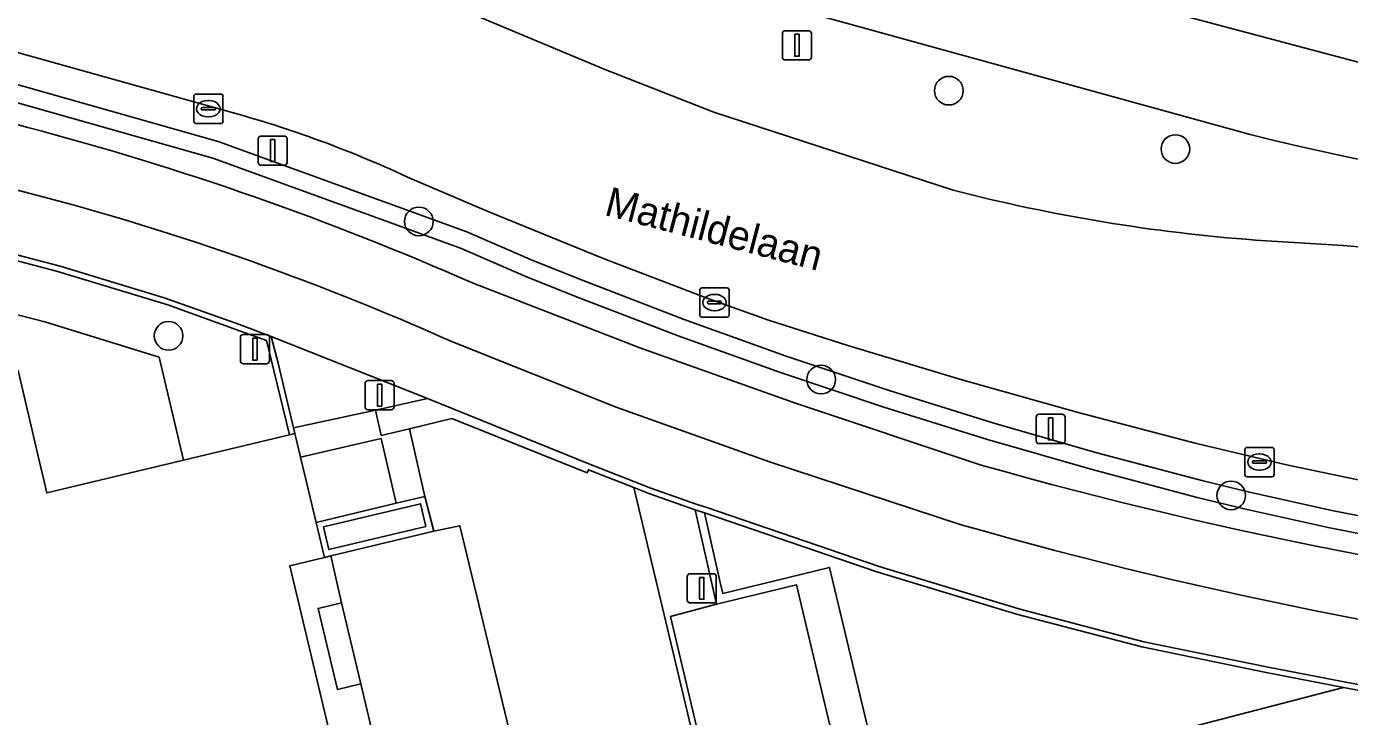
# Model space of a CAD drawing. Extents: x 160675 to 161153, y 383241 to 383714.
# Drawn here: x 160904.77 to 160949.96, y 383538.04 to 383561.62 of the extents above; entities that cross this region are included whole.
import ezdxf

# ---------------------------------------------------------------- set-up
doc = ezdxf.new("R2010")
doc.units = 0
for name, color, linetype in [('IMGEO_Berm_groen', 7, 'Continuous'), ('IMGEO_Boom', 7, 'Continuous'), ('IMGEO_Fietspad_gesloten', 7, 'Continuous'), ('IMGEO_Groenvoorziening', 7, 'Continuous'), ('IMGEO_Haag', 7, 'Continuous'), ('IMGEO_Kolk', 7, 'Continuous'), ('IMGEO_Lichtmast', 7, 'Continuous'), ('IMGEO_Muur', 7, 'Continuous'), ('IMGEO_Openbare_ruimte_label', 7, 'Continuous'), ('IMGEO_OVBaan_gesloten', 7, 'Continuous'), ('IMGEO_Pand', 7, 'Continuous'), ('IMGEO_Parkeervlak_open', 7, 'Continuous'), ('IMGEO_Rijbaan_lokaal_gesloten', 7, 'Continuous'), ('IMGEO_Rijbaan_lokaal_open', 7, 'Continuous'), ('IMGEO_Voetpad_op_trap', 7, 'Continuous'), ('IMGEO_Voetpad_open', 7, 'Continuous')]:
    doc.layers.add(name, color=color, linetype=linetype)

msp = doc.modelspace()

# ---------------------------------------------------------------- linework, layer by layer
at = {"layer": 'IMGEO_Berm_groen'}
for points in [[(160946.568, 383557.927), (160870.684, 383578.867)], [(160877.407, 383567.315), (160911.318, 383557.69), (160919.816, 383554.602), (160922.07, 383553.628), (160923.782, 383552.939), (160927.24, 383551.612), (160930.725, 383550.359), (160934.237, 383549.182), (160937.774, 383548.081), (160941.333, 383547.057), (160944.917, 383546.109), (160946.496, 383545.722), (160949.354, 383545.086), (160952.227, 383544.527)], [(160952.121, 383543.937), (160949.232, 383544.498), (160946.36, 383545.138), (160944.763, 383545.529), (160941.173, 383546.479), (160937.602, 383547.507), (160934.053, 383548.612), (160930.529, 383549.793), (160927.032, 383551.05), (160923.562, 383552.381), (160921.832, 383553.078), (160919.594, 383554.044), (160911.134, 383557.118), (160877.247, 383566.736)], [(160877.012, 383565.887), (160904.814, 383558.169)], [(160918.949, 383562.487), (160924.508, 383560.159), (160928.246, 383558.692), (160936.421, 383556.028)], [(160911.387, 383558.791), (160899.725, 383562.047)], [(160924.508, 383553.676), (160920.566, 383555.292), (160917.783, 383556.475)], [(160946.753, 383554.323), (160949.749, 383554.139), (160953.703, 383553.792), (160955.745, 383553.521)], [(160963.712, 383543.929), (160962.174, 383544.134), (160958.901, 383544.607), (160954.757, 383545.293), (160950.907, 383545.998), (160947.811, 383546.648), (160944.738, 383547.376), (160940.695, 383548.433), (160936.687, 383549.561), (160932.828, 383550.717), (160930.113, 383551.585), (160927.984, 383552.348), (160924.508, 383553.676)], [(160920.031, 383552.846), (160925.725, 383550.641), (160931.005, 383548.758), (160937.384, 383546.634)]]:
    msp.add_lwpolyline(points, dxfattribs=at)
for centre, radius, start, end in [((160901.669, 383521.963), 38.088, 64.9714, 75.2178), ((160878.698, 383459.098), 102.456, 66.20752, 75.23218), ((160969.146, 383648.782), 93.619, 256.04461, 272.62543), ((160951.121, 383612.952), 58.792, 255.52003, 265.73883), ((160978.636, 383692.084), 151.187, 254.16588, 264.20861)]:
    msp.add_arc(centre, radius, start, end, dxfattribs=at)
at = {"layer": 'IMGEO_Boom'}
for centre in [(160936.275, 383559.427), (160944.015, 383557.431), (160918.172, 383554.958), (160909.623, 383551.05), (160931.915, 383549.555), (160945.921, 383545.599)]:
    msp.add_circle(centre, 0.489, dxfattribs=at)
at = {"layer": 'IMGEO_Fietspad_gesloten'}
for points in [[(160904.814, 383558.169), (160877.012, 383565.887), (160875.567, 383566.288), (160873.601, 383566.834), (160872.54, 383567.128), (160754.374, 383598.874)], [(160937.384, 383546.634), (160931.005, 383548.758), (160925.725, 383550.641), (160920.031, 383552.846)], [(160919.266, 383550.863), (160924.913, 383548.61), (160930.147, 383546.745), (160936.693, 383544.597)]]:
    msp.add_lwpolyline(points, dxfattribs=at)
for centre, radius, start, end in [((160878.698, 383459.098), 102.456, 66.20752, 75.23218), ((160881.804, 383467.296), 91.58, 65.85393, 75.70457), ((160978.636, 383692.084), 151.187, 254.16588, 264.20861), ((160979.162, 383693.061), 154.418, 254.03661, 263.90206)]:
    msp.add_arc(centre, radius, start, end, dxfattribs=at)
at = {"layer": 'IMGEO_Groenvoorziening'}
for points in [[(160952.227, 383544.527), (160949.354, 383545.086), (160946.496, 383545.722), (160944.917, 383546.109), (160941.333, 383547.057), (160937.774, 383548.081), (160934.237, 383549.182), (160930.725, 383550.359), (160927.24, 383551.612), (160923.782, 383552.939), (160922.07, 383553.628), (160919.816, 383554.602), (160911.318, 383557.69), (160877.407, 383567.315)], [(160877.247, 383566.736), (160911.134, 383557.118), (160919.594, 383554.044), (160921.832, 383553.078), (160923.562, 383552.381), (160927.032, 383551.05), (160930.529, 383549.793), (160934.053, 383548.612), (160937.602, 383547.507), (160941.173, 383546.479), (160944.763, 383545.529), (160946.36, 383545.138), (160949.232, 383544.498), (160952.121, 383543.937)]]:
    msp.add_lwpolyline(points, dxfattribs=at)
for points in [[(160898.183, 383555.263), (160897.705, 383553.477), (160898.647, 383553.196), (160898.676, 383553.288), (160904.25, 383551.83), (160905.399, 383551.525), (160909.301, 383550.316), (160910.13, 383546.802), (160913.753, 383547.673), (160913.116, 383550.287), (160912.969, 383550.889), (160912.211, 383551.165), (160909.597, 383552.11), (160905.791, 383553.265)], [(160914.917, 383544.524), (160915.101, 383543.748), (160918.409, 383544.536), (160918.225, 383545.312)], [(160927.934, 383545.001), (160928.47, 383542.621), (160928.556, 383542.241), (160932.199, 383543.135), (160934.144, 383534.982), (160949.761, 383539.035), (160947.11, 383539.546), (160942.863, 383540.421), (160938.591, 383541.539), (160933.821, 383542.992)], [(160915.531, 383541.927), (160914.733, 383541.738), (160915.39, 383538.969), (160916.187, 383539.158)]]:
    msp.add_lwpolyline(points, close=True, dxfattribs=at)
at = {"layer": 'IMGEO_Haag'}
for points in [[(160952.227, 383544.527), (160949.354, 383545.086), (160946.496, 383545.722), (160944.917, 383546.109), (160941.333, 383547.057), (160937.774, 383548.081), (160934.237, 383549.182), (160930.725, 383550.359), (160927.24, 383551.612), (160923.782, 383552.939), (160922.07, 383553.628), (160919.816, 383554.602), (160911.318, 383557.69), (160877.407, 383567.315)], [(160877.247, 383566.736), (160911.134, 383557.118), (160919.594, 383554.044), (160921.832, 383553.078), (160923.562, 383552.381), (160927.032, 383551.05), (160930.529, 383549.793), (160934.053, 383548.612), (160937.602, 383547.507), (160941.173, 383546.479), (160944.763, 383545.529), (160946.36, 383545.138), (160949.232, 383544.498), (160952.121, 383543.937)]]:
    msp.add_lwpolyline(points, dxfattribs=at)
at = {"layer": 'IMGEO_Kolk'}
for p, q in [((160910.482, 383558.384), (160910.482, 383559.236)), ((160910.557, 383559.31), (160911.409, 383559.31)), ((160910.97, 383559.09), (160910.995, 383559.09)), ((160911.483, 383559.236), (160911.483, 383558.384)), ((160910.741, 383558.804), (160910.741, 383558.816)), ((160911.179, 383558.767), (160910.781, 383558.767)), ((160910.784, 383558.853), (160911.182, 383558.853)), ((160910.993, 383558.53), (160910.968, 383558.53)), ((160911.225, 383558.816), (160911.225, 383558.804)), ((160911.409, 383558.31), (160910.557, 383558.31)), ((160927.844, 383552.688), (160928.696, 383552.688)), ((160927.769, 383551.762), (160927.769, 383552.614)), ((160928.028, 383552.182), (160928.028, 383552.194)), ((160928.071, 383552.231), (160928.469, 383552.231)), ((160928.257, 383552.468), (160928.282, 383552.468)), ((160928.512, 383552.194), (160928.512, 383552.182)), ((160928.77, 383552.614), (160928.77, 383551.762)), ((160928.466, 383552.145), (160928.068, 383552.145)), ((160928.28, 383551.908), (160928.255, 383551.908)), ((160928.696, 383551.688), (160927.844, 383551.688)), ((160946.461, 383547.237), (160947.313, 383547.237)), ((160946.386, 383546.311), (160946.386, 383547.163)), ((160946.645, 383546.731), (160946.645, 383546.743)), ((160946.688, 383546.78), (160947.086, 383546.78)), ((160946.874, 383547.017), (160946.899, 383547.017)), ((160947.129, 383546.743), (160947.129, 383546.731)), ((160947.387, 383547.163), (160947.387, 383546.311)), ((160947.083, 383546.694), (160946.685, 383546.694)), ((160946.897, 383546.457), (160946.872, 383546.457)), ((160947.313, 383546.237), (160946.461, 383546.237))]:
    msp.add_line(p, q, dxfattribs=at)
for points in [[(160910.482, 383558.384), (160910.482, 383559.236)], [(160910.557, 383559.31), (160911.409, 383559.31)], [(160911.483, 383559.236), (160911.483, 383558.384)], [(160911.409, 383558.31), (160910.557, 383558.31)], [(160927.844, 383552.688), (160928.696, 383552.688)], [(160927.769, 383551.762), (160927.769, 383552.614)], [(160928.77, 383552.614), (160928.77, 383551.762)], [(160928.696, 383551.688), (160927.844, 383551.688)], [(160946.461, 383547.237), (160947.313, 383547.237)], [(160946.386, 383546.311), (160946.386, 383547.163)], [(160947.387, 383547.163), (160947.387, 383546.311)], [(160947.313, 383546.237), (160946.461, 383546.237)]]:
    msp.add_lwpolyline(points, dxfattribs=at)
for centre, radius, start, end in [((160910.559, 383559.234), 0.0765, 91.552, 178.448), ((160910.559, 383559.234), 0.0765, 91.552, 178.448), ((160911.407, 383559.234), 0.0765, 1.552, 88.448), ((160911.407, 383559.234), 0.0765, 1.552, 88.448), ((160910.781, 383558.813), 0.0403, 85.8775, 175.7526), ((160910.778, 383558.803), 0.0366, 178.938, 274.7102), ((160911.182, 383558.81), 0.043, 264.8664, 352.4533), ((160911.186, 383558.815), 0.0386, 1.7309, 96.639), ((160910.559, 383558.386), 0.0765, 181.552, 268.448), ((160910.559, 383558.386), 0.0765, 181.552, 268.448), ((160911.407, 383558.386), 0.0765, 271.552, 358.448), ((160911.407, 383558.386), 0.0765, 271.552, 358.448), ((160927.846, 383552.612), 0.0765, 91.552, 178.448), ((160927.846, 383552.612), 0.0765, 91.552, 178.448), ((160928.694, 383552.612), 0.0765, 1.552, 88.448), ((160928.694, 383552.612), 0.0765, 1.552, 88.448), ((160928.068, 383552.191), 0.0403, 85.8775, 175.7526), ((160928.065, 383552.181), 0.0366, 178.938, 274.7102), ((160928.469, 383552.188), 0.043, 264.8664, 352.4533), ((160928.473, 383552.193), 0.0386, 1.7309, 96.639), ((160927.846, 383551.764), 0.0765, 181.552, 268.448), ((160927.846, 383551.764), 0.0765, 181.552, 268.448), ((160928.694, 383551.764), 0.0765, 271.552, 358.448), ((160928.694, 383551.764), 0.0765, 271.552, 358.448), ((160946.463, 383547.161), 0.0765, 91.552, 178.448), ((160946.463, 383547.161), 0.0765, 91.552, 178.448), ((160947.311, 383547.161), 0.0765, 1.552, 88.448), ((160947.311, 383547.161), 0.0765, 1.552, 88.448), ((160946.685, 383546.74), 0.0403, 85.8775, 175.7526), ((160947.09, 383546.742), 0.0386, 1.7309, 96.639), ((160946.463, 383546.313), 0.0765, 181.552, 268.448), ((160946.463, 383546.313), 0.0765, 181.552, 268.448), ((160946.682, 383546.73), 0.0366, 178.938, 274.7102), ((160947.086, 383546.737), 0.043, 264.8664, 352.4533), ((160947.311, 383546.313), 0.0765, 271.552, 358.448), ((160947.311, 383546.313), 0.0765, 271.552, 358.448)]:
    msp.add_arc(centre, radius, start, end, dxfattribs=at)
for centre, major_axis, ratio, start_param, end_param in [((160910.969, 383558.81), (-0.387, 0.002), 0.722429, 4.712389, 7.853982), ((160910.994, 383558.81), (-0.39, 0.002), 0.717154, 1.570796, 4.712389), ((160928.256, 383552.188), (-0.387, 0.002), 0.722429, 4.712389, 7.853982), ((160928.281, 383552.188), (-0.39, 0.002), 0.717154, 1.570796, 4.712389), ((160946.873, 383546.737), (-0.387, 0.002), 0.722429, 4.712389, 7.853982), ((160946.898, 383546.737), (-0.39, 0.002), 0.717154, 1.570796, 4.712389)]:
    msp.add_ellipse(centre, major_axis=major_axis, ratio=ratio, start_param=start_param, end_param=end_param, dxfattribs=at)
at = {"layer": 'IMGEO_Lichtmast'}
for p, q in [((160930.591, 383560.577), (160930.591, 383561.377)), ((160930.591, 383561.377), (160930.591, 383560.577)), ((160930.691, 383561.477), (160931.481, 383561.477)), ((160931.481, 383561.477), (160930.691, 383561.477)), ((160931.581, 383561.377), (160931.581, 383560.577)), ((160931.581, 383560.577), (160931.581, 383561.377)), ((160931.481, 383560.477), (160930.691, 383560.477)), ((160930.691, 383560.477), (160931.481, 383560.477)), ((160912.685, 383556.978), (160912.685, 383557.778)), ((160912.685, 383557.778), (160912.685, 383556.978)), ((160912.785, 383557.878), (160913.575, 383557.878)), ((160913.575, 383557.878), (160912.785, 383557.878)), ((160913.675, 383557.778), (160913.675, 383556.978)), ((160913.675, 383556.978), (160913.675, 383557.778)), ((160913.575, 383556.878), (160912.785, 383556.878)), ((160912.785, 383556.878), (160913.575, 383556.878)), ((160912.078, 383550.197), (160912.078, 383550.997)), ((160912.078, 383550.997), (160912.078, 383550.197)), ((160912.178, 383551.097), (160912.968, 383551.097)), ((160912.968, 383551.097), (160912.178, 383551.097)), ((160913.068, 383550.997), (160913.068, 383550.197)), ((160913.068, 383550.197), (160913.068, 383550.997)), ((160912.968, 383550.097), (160912.178, 383550.097)), ((160912.178, 383550.097), (160912.968, 383550.097)), ((160916.436, 383549.524), (160917.226, 383549.524)), ((160917.226, 383549.524), (160916.436, 383549.524)), ((160916.336, 383548.624), (160916.336, 383549.424)), ((160916.336, 383549.424), (160916.336, 383548.624)), ((160917.326, 383549.424), (160917.326, 383548.624)), ((160917.326, 383548.624), (160917.326, 383549.424)), ((160917.226, 383548.524), (160916.436, 383548.524)), ((160916.436, 383548.524), (160917.226, 383548.524)), ((160939.257, 383547.469), (160939.257, 383548.269)), ((160939.257, 383548.269), (160939.257, 383547.469)), ((160939.357, 383548.369), (160940.147, 383548.369)), ((160940.147, 383548.369), (160939.357, 383548.369)), ((160940.247, 383548.269), (160940.247, 383547.469)), ((160940.247, 383547.469), (160940.247, 383548.269)), ((160940.147, 383547.369), (160939.357, 383547.369)), ((160939.357, 383547.369), (160940.147, 383547.369)), ((160927.341, 383542.023), (160927.341, 383542.823)), ((160927.341, 383542.823), (160927.341, 383542.023)), ((160927.441, 383542.923), (160928.231, 383542.923)), ((160928.231, 383542.923), (160927.441, 383542.923)), ((160928.331, 383542.823), (160928.331, 383542.023)), ((160928.331, 383542.023), (160928.331, 383542.823)), ((160928.231, 383541.923), (160927.441, 383541.923)), ((160927.441, 383541.923), (160928.231, 383541.923))]:
    msp.add_line(p, q, dxfattribs=at)
for points in [[(160931.011, 383561.352), (160931.161, 383561.352), (160931.161, 383560.602), (160931.011, 383560.602), (160931.011, 383561.352)], [(160913.105, 383557.753), (160913.255, 383557.753), (160913.255, 383557.003), (160913.105, 383557.003), (160913.105, 383557.753)], [(160912.498, 383550.972), (160912.648, 383550.972), (160912.648, 383550.222), (160912.498, 383550.222), (160912.498, 383550.972)], [(160916.756, 383549.399), (160916.906, 383549.399), (160916.906, 383548.649), (160916.756, 383548.649), (160916.756, 383549.399)], [(160939.677, 383548.244), (160939.827, 383548.244), (160939.827, 383547.494), (160939.677, 383547.494), (160939.677, 383548.244)], [(160927.761, 383542.798), (160927.911, 383542.798), (160927.911, 383542.048), (160927.761, 383542.048), (160927.761, 383542.798)]]:
    msp.add_lwpolyline(points, dxfattribs=at)
for centre, start, end in [((160930.691, 383561.377), 90, 180), ((160930.691, 383561.377), 90, 180), ((160931.481, 383561.377), 0, 90), ((160931.481, 383561.377), 360, 90), ((160930.691, 383560.577), 180, 270), ((160930.691, 383560.577), 180, 270), ((160931.481, 383560.577), 270, 0), ((160931.481, 383560.577), 270, 0), ((160912.785, 383557.778), 90, 180), ((160912.785, 383557.778), 90, 180), ((160913.575, 383557.778), 0, 90), ((160913.575, 383557.778), 360, 90), ((160912.785, 383556.978), 180, 270), ((160912.785, 383556.978), 180, 270), ((160913.575, 383556.978), 270, 0), ((160913.575, 383556.978), 270, 0), ((160912.178, 383550.997), 90, 180), ((160912.178, 383550.997), 90, 180), ((160912.968, 383550.997), 0, 90), ((160912.968, 383550.997), 360, 90), ((160912.178, 383550.197), 180, 270), ((160912.178, 383550.197), 180, 270), ((160912.968, 383550.197), 270, 0), ((160912.968, 383550.197), 270, 0), ((160916.436, 383549.424), 90, 180), ((160916.436, 383549.424), 90, 180), ((160917.226, 383549.424), 0, 90), ((160917.226, 383549.424), 360, 90), ((160916.436, 383548.624), 180, 270), ((160916.436, 383548.624), 180, 270), ((160917.226, 383548.624), 270, 0), ((160917.226, 383548.624), 270, 0), ((160939.357, 383548.269), 90, 180), ((160939.357, 383548.269), 90, 180), ((160940.147, 383548.269), 0, 90), ((160940.147, 383548.269), 360, 90), ((160939.357, 383547.469), 180, 270), ((160939.357, 383547.469), 180, 270), ((160940.147, 383547.469), 270, 0), ((160940.147, 383547.469), 270, 0), ((160927.441, 383542.823), 90, 180), ((160927.441, 383542.823), 90, 180), ((160928.231, 383542.823), 0, 90), ((160928.231, 383542.823), 360, 90), ((160927.441, 383542.023), 180, 270), ((160927.441, 383542.023), 180, 270), ((160928.231, 383542.023), 270, 0), ((160928.231, 383542.023), 270, 0)]:
    msp.add_arc(centre, 0.1, start, end, dxfattribs=at)
at = {"layer": 'IMGEO_Muur'}
for points in [[(160897.457, 383553.323), (160898.593, 383553.004), (160898.647, 383553.196), (160897.705, 383553.477), (160898.183, 383555.263), (160905.791, 383553.265), (160909.597, 383552.11), (160912.211, 383551.165), (160912.969, 383550.889), (160913.116, 383550.287), (160913.753, 383547.673), (160913.938, 383547.717), (160913.896, 383547.906), (160913.371, 383550.116), (160913.126, 383551.032), (160913.033, 383551.067), (160912.048, 383551.434), (160909.9, 383552.197), (160909.478, 383552.344), (160905.919, 383553.429), (160898.038, 383555.497)], [(160918.681, 383544.372), (160918.38, 383545.562), (160917.394, 383545.333), (160914.668, 383544.677), (160914.955, 383543.48), (160915.164, 383543.53)], [(160915.101, 383543.748), (160914.917, 383544.524), (160918.225, 383545.312), (160918.409, 383544.536)]]:
    msp.add_lwpolyline(points, close=True, dxfattribs=at)
msp.add_lwpolyline([(160952.679, 383538.681), (160949.834, 383539.214), (160947.183, 383539.724), (160942.936, 383540.6), (160938.664, 383541.718), (160933.895, 383543.171), (160928.008, 383545.18), (160927.679, 383545.288), (160926.102, 383545.843), (160924.038, 383546.65), (160918.464, 383548.913), (160916.694, 383548.509), (160916.889, 383547.65), (160917.852, 383547.878), (160919.303, 383548.225), (160923.918, 383546.365), (160923.965, 383546.472), (160925.515, 383545.865), (160926.029, 383545.664), (160927.606, 383545.109), (160927.934, 383545.001), (160933.821, 383542.992), (160938.591, 383541.539), (160942.863, 383540.421), (160947.11, 383539.546), (160949.761, 383539.035), (160952.606, 383538.502)], dxfattribs=at)
at = {"layer": 'IMGEO_OVBaan_gesloten'}
for points in [[(160760.567, 383616.024), (160759.368, 383616.453), (160756.884, 383613.99), (160761.763, 383612.059), (160766.781, 383610.37), (160770.415, 383609.332), (160774.938, 383608.123), (160890.249, 383576.873), (160942.076, 383562.592), (160950.815, 383560.255), (160956.785, 383559.216), (160962.841, 383558.697), (160968.725, 383558.524), (160975.387, 383558.61), (160977.148, 383558.794), (160977.505, 383562.304), (160973.835, 383561.901)], [(160973.434, 383555.262), (160976.812, 383555.49), (160977.148, 383558.794), (160975.387, 383558.61), (160968.725, 383558.524), (160962.841, 383558.697), (160956.785, 383559.216), (160950.815, 383560.255), (160942.076, 383562.592), (160890.249, 383576.873), (160774.938, 383608.123), (160770.415, 383609.332), (160766.781, 383610.37), (160761.763, 383612.059), (160756.884, 383613.99)], [(160765.95, 383607.15), (160797.835, 383598.49), (160870.684, 383578.867), (160946.568, 383557.927)]]:
    msp.add_lwpolyline(points, dxfattribs=at)
msp.add_arc((160969.146, 383648.782), 93.619, 256.04461, 272.62543, dxfattribs=at)
at = {"layer": 'IMGEO_Pand'}
msp.add_lwpolyline([(160918.775, 383502.03), (160918.011, 383505.128), (160922.567, 383506.212), (160913.765, 383543.194), (160914.955, 383543.48), (160914.668, 383544.677), (160914.132, 383546.908), (160913.938, 383547.717), (160913.753, 383547.673), (160910.13, 383546.802), (160905.464, 383545.682), (160905.215, 383546.74), (160904.484, 383549.867)], dxfattribs=at)
at = {"layer": 'IMGEO_Parkeervlak_open'}
for points in [[(160918.681, 383544.372), (160915.164, 383543.53), (160915.531, 383541.927), (160916.187, 383539.158), (160916.563, 383537.582), (160917.929, 383531.696), (160918.367, 383530.033), (160920.797, 383519.84), (160921.166, 383518.194), (160923.632, 383508.016), (160923.604, 383508.009), (160923.998, 383506.38), (160928.346, 383507.404), (160925.219, 383520.775), (160924.486, 383524.178), (160919.572, 383544.563)], [(160928.34, 383541.877), (160927.575, 383541.674), (160926.763, 383541.459), (160929.874, 383528.32), (160931.293, 383522.198), (160934.493, 383508.833), (160938.8, 383509.852), (160935.678, 383523.06), (160933.672, 383531.613), (160931.069, 383542.544)]]:
    msp.add_lwpolyline(points, close=True, dxfattribs=at)
at = {"layer": 'IMGEO_Rijbaan_lokaal_gesloten'}
for points in [[(160860.355, 383572.895), (160871.092, 383569.968), (160874.194, 383569.11), (160876.194, 383568.556), (160877.64, 383568.157), (160899.725, 383562.047), (160911.387, 383558.791)], [(160936.421, 383556.028), (160928.246, 383558.692), (160924.508, 383560.159), (160918.949, 383562.487)], [(160917.783, 383556.475), (160920.566, 383555.292), (160924.508, 383553.676), (160927.984, 383552.348), (160930.113, 383551.585), (160932.828, 383550.717), (160936.687, 383549.561), (160940.695, 383548.433), (160944.738, 383547.376), (160947.811, 383546.648), (160950.907, 383545.998), (160954.757, 383545.293), (160958.901, 383544.607), (160962.174, 383544.134), (160963.712, 383543.929)], [(160955.745, 383553.521), (160953.703, 383553.792), (160949.749, 383554.139), (160946.753, 383554.323)]]:
    msp.add_lwpolyline(points, dxfattribs=at)
for centre, radius, start, end in [((160901.669, 383521.963), 38.088, 64.9714, 75.2178), ((160951.121, 383612.952), 58.792, 255.52003, 265.73883)]:
    msp.add_arc(centre, radius, start, end, dxfattribs=at)
at = {"layer": 'IMGEO_Rijbaan_lokaal_open'}
for points in [[(160925.515, 383545.865), (160923.965, 383546.472), (160923.918, 383546.365), (160919.303, 383548.225), (160917.852, 383547.878), (160918.38, 383545.562), (160918.681, 383544.372), (160919.572, 383544.563), (160924.486, 383524.178), (160925.219, 383520.775), (160928.346, 383507.404), (160934.325, 383508.794), (160931.128, 383522.157), (160929.71, 383528.273)], [(160927.606, 383545.109), (160926.029, 383545.664), (160925.515, 383545.865), (160929.71, 383528.273), (160931.128, 383522.157), (160934.325, 383508.794), (160934.493, 383508.833), (160931.293, 383522.198), (160929.874, 383528.32), (160926.763, 383541.459), (160927.575, 383541.674), (160928.34, 383541.877)]]:
    msp.add_lwpolyline(points, close=True, dxfattribs=at)
at = {"layer": 'IMGEO_Voetpad_op_trap'}
msp.add_lwpolyline([(160917.852, 383547.878), (160916.889, 383547.65), (160916.694, 383548.509), (160913.896, 383547.906), (160913.938, 383547.717), (160914.132, 383546.908), (160916.883, 383547.537), (160917.394, 383545.333), (160918.38, 383545.562)], close=True, dxfattribs=at)
at = {"layer": 'IMGEO_Voetpad_open'}
for points in [[(160898.038, 383555.497), (160905.919, 383553.429), (160909.478, 383552.344), (160909.9, 383552.197), (160912.048, 383551.434), (160913.033, 383551.067), (160913.126, 383551.032), (160918.464, 383548.913), (160924.038, 383546.65), (160926.102, 383545.843), (160927.679, 383545.288), (160928.008, 383545.18), (160933.895, 383543.171), (160938.664, 383541.718), (160942.936, 383540.6), (160947.183, 383539.724), (160949.834, 383539.214), (160952.679, 383538.681)], [(160936.693, 383544.597), (160930.147, 383546.745), (160924.913, 383548.61), (160919.266, 383550.863)], [(160952.606, 383538.502), (160949.761, 383539.035), (160934.144, 383534.982), (160932.199, 383543.135), (160928.556, 383542.241), (160928.47, 383542.621), (160927.934, 383545.001), (160927.606, 383545.109), (160928.34, 383541.877), (160931.069, 383542.544), (160933.672, 383531.613)], [(160916.563, 383537.582), (160916.187, 383539.158), (160915.39, 383538.969), (160914.733, 383541.738), (160915.531, 383541.927), (160915.164, 383543.53), (160914.955, 383543.48), (160913.765, 383543.194), (160922.567, 383506.212)]]:
    msp.add_lwpolyline(points, dxfattribs=at)
for points in [[(160898.647, 383553.196), (160898.593, 383553.004), (160898.278, 383551.843), (160898.231, 383551.646), (160897.265, 383551.906), (160896.146, 383547.886), (160904.484, 383549.867), (160905.215, 383546.74), (160905.464, 383545.682), (160910.13, 383546.802), (160909.301, 383550.316), (160905.399, 383551.525), (160904.25, 383551.83), (160898.676, 383553.288)], [(160913.126, 383551.032), (160913.371, 383550.116), (160913.896, 383547.906), (160916.694, 383548.509), (160918.464, 383548.913)], [(160914.132, 383546.908), (160914.668, 383544.677), (160917.394, 383545.333), (160916.883, 383547.537)]]:
    msp.add_lwpolyline(points, close=True, dxfattribs=at)
for centre, radius, start, end in [((160881.804, 383467.296), 91.58, 65.85393, 75.70457), ((160979.162, 383693.061), 154.418, 254.03661, 263.90206)]:
    msp.add_arc(centre, radius, start, end, dxfattribs=at)

# ---------------------------------------------------------------- texts
at = {"layer": 'IMGEO_Openbare_ruimte_label'}
msp.add_text('Mathildelaan', height=1, rotation=345.3381, dxfattribs=at).set_placement((160924.471, 383555.186))

doc.saveas('drawing.dxf')
